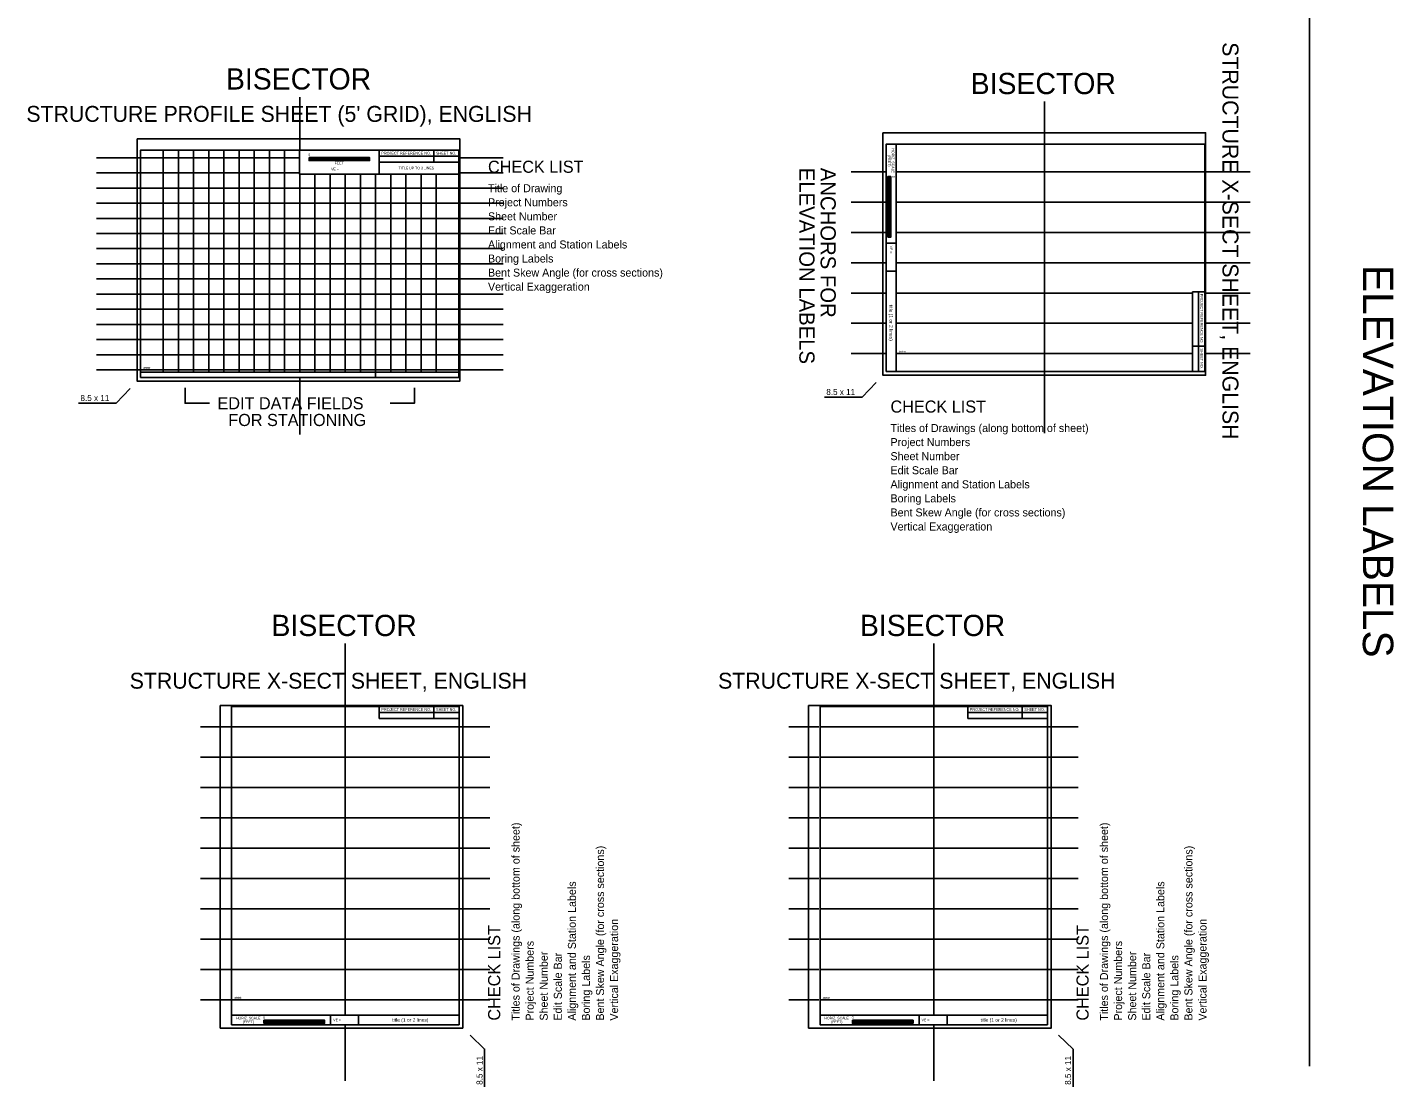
# Model space of a CAD drawing. Extents: x 278618 to 280654, y 171155 to 171855.
# Drawn here: x 278748.3 to 279198.9, y 171155.2 to 171504.7 of the extents above; entities that cross this region are included whole.
import ezdxf

# ---------------------------------------------------------------- set-up
doc = ezdxf.new("R2010")
doc.units = 0
for name, color, linetype in [('Geotech Sheets and Borders Cell', 7, 'Continuous'), ('Prop Strc Sect_ Grid - minor', 7, 'Continuous'), ('Prop Strc Sect_ Misc - Drafting Aid (dashed line)', 7, 'Continuous'), ('Prop Strc Sect_ Misc - User Comment (Tx - large)', 7, 'Continuous'), ('Prop Strc Sect_ Misc - User Comment (Tx - small)', 7, 'Continuous'), ('Scratch_Level_0', 7, 'Continuous'), ('Scratch_Level_2', 7, 'Continuous'), ('Scratch_Level_4', 7, 'Continuous'), ('Sheet Dot Grid CELL', 7, 'Continuous'), ('Sheet Plot Border Inside CELL', 7, 'Continuous')]:
    doc.layers.add(name, color=color, linetype=linetype)

msp = doc.modelspace()

# ---------------------------------------------------------------- linework, layer by layer
at = {"layer": 'Geotech Sheets and Borders Cell'}
for p, q in [((278864.34, 171462.15), (278890.63, 171462.15)), ((278882.35, 171464.15), (278882.35, 171460.15)), ((279034.8, 171433.49), (279031.59, 171433.49)), ((279034.8, 171433.49), (279031.59, 171433.49)), ((279034.8, 171424.26), (279031.59, 171424.26)), ((279134.59, 171417.45), (279134.59, 171391.15)), ((279136.59, 171399.44), (279132.59, 171399.44)), ((278785.63, 171390.92), (278890.63, 171390.92)), ((278864.36, 171278.64), (278890.66, 171278.64)), ((278882.37, 171280.64), (278882.37, 171276.64)), ((279058.42, 171278.64), (279084.72, 171278.64)), ((279076.43, 171280.64), (279076.43, 171276.64)), ((278848.32, 171178.85), (278848.32, 171175.64)), ((278848.32, 171178.85), (278848.32, 171175.64)), ((278857.55, 171178.85), (278857.55, 171175.64)), ((279042.38, 171178.85), (279042.38, 171175.64)), ((279042.38, 171178.85), (279042.38, 171175.64)), ((279051.61, 171178.85), (279051.61, 171175.64))]:
    msp.add_line(p, q, dxfattribs=at)
for points in [[(278890.63, 171464.15), (278890.63, 171389.15), (278785.63, 171389.15), (278785.63, 171464.15)], [(278838.04, 171456.25), (278890.63, 171456.25), (278890.63, 171464.15), (278838.04, 171464.15)], [(278864.34, 171460.15), (278890.63, 171460.15), (278890.63, 171464.15), (278864.34, 171464.15)], [(278864.34, 171464.15), (278890.63, 171464.15), (278890.63, 171456.25), (278864.34, 171456.25)], [(279136.59, 171466.15), (279136.59, 171391.15), (279031.59, 171391.15), (279031.59, 171466.15)], [(279034.8, 171466.15), (279034.8, 171391.15), (279031.59, 171391.15), (279031.59, 171466.15)], [(278841.19, 171461.69), (278861.19, 171461.69), (278861.19, 171460.69), (278841.19, 171460.69)], [(278841.19, 171461.69), (278851.19, 171461.69), (278851.19, 171461.19), (278841.19, 171461.19)], [(278851.19, 171461.19), (278861.19, 171461.19), (278861.19, 171460.69), (278851.19, 171460.69)], [(279033.09, 171455.47), (279033.09, 171435.47), (279032.09, 171435.47), (279032.09, 171455.47)], [(279033.09, 171455.47), (279033.09, 171445.47), (279032.59, 171445.47), (279032.59, 171455.47)], [(279032.59, 171445.47), (279032.59, 171435.47), (279032.09, 171435.47), (279032.09, 171445.47)], [(279132.59, 171417.45), (279132.59, 171391.15), (279136.59, 171391.15), (279136.59, 171417.45)], [(278815.66, 171280.64), (278890.66, 171280.64), (278890.66, 171175.64), (278815.66, 171175.64)], [(278864.36, 171276.64), (278890.66, 171276.64), (278890.66, 171280.64), (278864.36, 171280.64)], [(279009.72, 171280.64), (279084.72, 171280.64), (279084.72, 171175.64), (279009.72, 171175.64)], [(279058.42, 171276.64), (279084.72, 171276.64), (279084.72, 171280.64), (279058.42, 171280.64)], [(278815.66, 171178.85), (278890.66, 171178.85), (278890.66, 171175.64), (278815.66, 171175.64)], [(279009.72, 171178.85), (279084.72, 171178.85), (279084.72, 171175.64), (279009.72, 171175.64)], [(278826.34, 171177.14), (278846.34, 171177.14), (278846.34, 171176.14), (278826.34, 171176.14)], [(278826.34, 171177.14), (278836.34, 171177.14), (278836.34, 171176.64), (278826.34, 171176.64)], [(278836.34, 171176.64), (278846.34, 171176.64), (278846.34, 171176.14), (278836.34, 171176.14)], [(279020.4, 171177.14), (279040.4, 171177.14), (279040.4, 171176.14), (279020.4, 171176.14)], [(279020.4, 171177.14), (279030.4, 171177.14), (279030.4, 171176.64), (279020.4, 171176.64)], [(279030.4, 171176.64), (279040.4, 171176.64), (279040.4, 171176.14), (279030.4, 171176.14)]]:
    msp.add_lwpolyline(points, close=True, dxfattribs=at)
at = {"layer": 'Prop Strc Sect_ Grid - minor'}
for p, q in [((279136.59, 171457.02), (279034.8, 171457.02)), ((279136.59, 171447.02), (279034.8, 171447.02)), ((279136.59, 171437.02), (279034.8, 171437.02)), ((279136.59, 171427.02), (279034.8, 171427.02)), ((279132.59, 171417.02), (279034.8, 171417.02)), ((279132.59, 171407.02), (279034.8, 171407.02)), ((279132.59, 171397.02), (279034.8, 171397.02)), ((278890.66, 171273.96), (278815.66, 171273.96)), ((279084.72, 171273.96), (279009.72, 171273.96)), ((278890.66, 171263.96), (278815.66, 171263.96)), ((279084.72, 171263.96), (279009.72, 171263.96)), ((278890.66, 171253.95), (278815.66, 171253.95)), ((279084.72, 171253.95), (279009.72, 171253.95)), ((278890.66, 171243.93), (278815.66, 171243.93)), ((279084.72, 171243.93), (279009.72, 171243.93)), ((278890.66, 171233.92), (278815.66, 171233.92)), ((279084.72, 171233.92), (279009.72, 171233.92)), ((278890.66, 171223.91), (278815.66, 171223.91)), ((279084.72, 171223.91), (279009.72, 171223.91)), ((278890.66, 171213.9), (278815.66, 171213.9)), ((279084.72, 171213.9), (279009.72, 171213.9)), ((278890.66, 171203.88), (278815.66, 171203.88)), ((279084.72, 171203.88), (279009.72, 171203.88)), ((278890.66, 171193.87), (278815.66, 171193.87)), ((279084.72, 171193.87), (279009.72, 171193.87)), ((278890.66, 171183.86), (278815.66, 171183.86)), ((279084.72, 171183.86), (279009.72, 171183.86))]:
    msp.add_line(p, q, dxfattribs=at)
at = {"layer": 'Prop Strc Sect_ Misc - Drafting Aid (dashed line)'}
for p, q in [((278838.13, 171481.66), (278838.13, 171464.15)), ((279083.74, 171480.14), (279083.74, 171370.82)), ((278787.47, 171461.65), (278771.08, 171461.65)), ((278890.63, 171461.65), (278905.18, 171461.65)), ((278787.47, 171456.65), (278771.08, 171456.65)), ((278838.13, 171456.25), (278838.13, 171390.92)), ((278890.63, 171456.65), (278905.18, 171456.65)), ((279031.59, 171457.02), (279019.97, 171457.02)), ((279036.88, 171457.02), (279034.8, 171457.02)), ((279151.56, 171457.02), (279134.64, 171457.02)), ((278787.47, 171451.65), (278771.08, 171451.65)), ((278888.79, 171451.65), (278905.18, 171451.65)), ((278787.47, 171446.65), (278771.08, 171446.65)), ((278888.79, 171446.65), (278905.18, 171446.65)), ((279031.59, 171447.02), (279019.97, 171447.02)), ((279036.88, 171447.02), (279034.8, 171447.02)), ((279151.56, 171447.02), (279134.64, 171447.02)), ((278787.47, 171441.65), (278771.08, 171441.65)), ((278888.79, 171441.65), (278905.18, 171441.65)), ((278787.47, 171436.65), (278771.08, 171436.65)), ((278888.79, 171436.65), (278905.18, 171436.65)), ((279031.59, 171437.02), (279019.97, 171437.02)), ((279036.88, 171437.02), (279034.8, 171437.02)), ((279151.56, 171437.02), (279134.64, 171437.02)), ((278787.47, 171431.65), (278771.08, 171431.65)), ((278888.79, 171431.65), (278905.18, 171431.65)), ((278787.47, 171426.65), (278771.08, 171426.65)), ((278888.79, 171426.65), (278905.18, 171426.65)), ((279031.59, 171427.02), (279019.97, 171427.02)), ((279036.88, 171427.02), (279034.8, 171427.02)), ((279151.56, 171427.02), (279134.64, 171427.02)), ((278787.47, 171421.65), (278771.08, 171421.65)), ((278888.79, 171421.65), (278905.18, 171421.65)), ((279031.59, 171417.02), (279019.97, 171417.02)), ((279036.88, 171417.02), (279034.8, 171417.02)), ((279151.56, 171417.02), (279136.59, 171417.02)), ((278787.47, 171416.65), (278771.08, 171416.65)), ((278888.79, 171416.65), (278905.18, 171416.65)), ((278787.47, 171411.65), (278771.08, 171411.65)), ((278888.79, 171411.65), (278905.18, 171411.65)), ((278787.47, 171406.65), (278771.08, 171406.65)), ((278888.79, 171406.65), (278905.18, 171406.65)), ((279031.59, 171407.02), (279019.97, 171407.02)), ((279036.88, 171407.02), (279034.8, 171407.02)), ((279151.56, 171407.02), (279136.59, 171407.02)), ((278787.47, 171401.65), (278771.08, 171401.65)), ((278888.79, 171401.65), (278905.18, 171401.65)), ((278787.47, 171396.65), (278771.08, 171396.65)), ((278888.79, 171396.65), (278905.18, 171396.65)), ((279031.59, 171397.02), (279019.97, 171397.02)), ((279036.88, 171397.02), (279034.8, 171397.02)), ((279151.56, 171397.02), (279136.59, 171397.02)), ((278787.47, 171391.65), (278771.08, 171391.65)), ((278888.79, 171391.65), (278905.18, 171391.65)), ((278838.13, 171389.15), (278838.13, 171370.32)), ((278853.16, 171301.38), (278853.16, 171178.85)), ((279047.22, 171301.38), (279047.22, 171178.85)), ((278805.36, 171273.96), (278815.26, 171273.96)), ((278890.88, 171273.96), (278900.79, 171273.96)), ((278999.42, 171273.96), (279009.32, 171273.96)), ((279084.94, 171273.97), (279094.84, 171273.97)), ((278805.36, 171263.96), (278815.26, 171263.96)), ((278890.88, 171263.96), (278900.79, 171263.96)), ((278999.42, 171263.96), (279009.32, 171263.96)), ((279084.94, 171263.96), (279094.84, 171263.96)), ((278805.36, 171253.95), (278815.26, 171253.95)), ((278890.88, 171253.95), (278900.79, 171253.95)), ((278999.42, 171253.95), (279009.32, 171253.95)), ((279084.94, 171253.95), (279094.84, 171253.95)), ((278805.36, 171243.93), (278815.26, 171243.93)), ((278890.88, 171243.93), (278900.79, 171243.93)), ((278999.42, 171243.93), (279009.32, 171243.93)), ((279084.94, 171243.93), (279094.84, 171243.93)), ((278805.36, 171233.92), (278815.26, 171233.92)), ((278890.88, 171233.92), (278900.79, 171233.92)), ((278999.42, 171233.92), (279009.32, 171233.92)), ((279084.94, 171233.92), (279094.84, 171233.92)), ((278805.36, 171223.91), (278815.26, 171223.91)), ((278890.88, 171223.91), (278900.79, 171223.91)), ((278999.42, 171223.91), (279009.32, 171223.91)), ((279084.94, 171223.91), (279094.84, 171223.91)), ((278805.36, 171213.9), (278815.26, 171213.9)), ((278890.88, 171213.9), (278900.79, 171213.9)), ((278999.42, 171213.9), (279009.32, 171213.9)), ((279084.94, 171213.9), (279094.84, 171213.9)), ((278805.36, 171203.88), (278815.26, 171203.88)), ((278890.88, 171203.88), (278900.79, 171203.88)), ((278999.42, 171203.88), (279009.32, 171203.88)), ((279084.94, 171203.88), (279094.84, 171203.88)), ((278805.36, 171193.87), (278815.26, 171193.87)), ((278890.88, 171193.87), (278900.79, 171193.87)), ((278999.42, 171193.87), (279009.32, 171193.87)), ((279084.94, 171193.87), (279094.84, 171193.87)), ((278805.36, 171183.86), (278815.26, 171183.86)), ((278890.88, 171183.86), (278900.79, 171183.86)), ((278999.42, 171183.86), (279009.32, 171183.86)), ((279084.94, 171183.86), (279094.84, 171183.86)), ((278853.16, 171175.64), (278853.16, 171157.13)), ((279047.22, 171175.64), (279047.22, 171157.13))]:
    msp.add_line(p, q, dxfattribs=at)
at = {"layer": 'Prop Strc Sect_ Misc - User Comment (Tx - large)'}
msp.add_line((279171.15, 171633.82), (279171.15, 171161.99), dxfattribs=at)
at = {"layer": 'Scratch_Level_0'}
for p, q in [((278890.92, 171467.9), (278890.92, 171467.9)), ((279136.88, 171469.9), (279136.88, 171469.9)), ((279030.48, 171389.9), (279030.48, 171389.9)), ((278784.52, 171387.9), (278784.52, 171387.9)), ((278811.91, 171280.93), (278811.91, 171280.93)), ((279005.97, 171280.93), (279005.97, 171280.93)), ((278891.91, 171174.53), (278891.91, 171174.53)), ((279085.97, 171174.53), (279085.97, 171174.53))]:
    msp.add_line(p, q, dxfattribs=at)
for points in [[(278765.21, 171380.71), (278777.63, 171380.71), (278782.22, 171385.51)], [(279011.17, 171382.71), (279023.6, 171382.71), (279028.19, 171387.51)], [(278899.1, 171155.22), (278899.1, 171167.64), (278894.3, 171172.24)], [(279093.16, 171155.22), (279093.16, 171167.64), (279088.36, 171172.24)]]:
    msp.add_lwpolyline(points, dxfattribs=at)
at = {"layer": 'Scratch_Level_4'}
for points in [[(278808.34, 171380.66), (278800.31, 171380.66), (278800.31, 171385.74)], [(278867.93, 171380.66), (278875.96, 171380.66), (278875.96, 171385.74)]]:
    msp.add_lwpolyline(points, dxfattribs=at)
at = {"layer": 'Sheet Dot Grid CELL'}
for p, q in [((278793.13, 171464.15), (278793.13, 171390.92)), ((278798.13, 171464.15), (278798.13, 171390.92)), ((278803.13, 171464.15), (278803.13, 171390.92)), ((278808.13, 171464.15), (278808.13, 171390.92)), ((278813.13, 171464.15), (278813.13, 171390.92)), ((278818.13, 171464.15), (278818.13, 171390.92)), ((278823.13, 171464.15), (278823.13, 171390.92)), ((278828.13, 171464.15), (278828.13, 171390.92)), ((278833.13, 171464.15), (278833.13, 171390.92)), ((278785.63, 171461.65), (278838.04, 171461.65)), ((278785.63, 171456.65), (278838.04, 171456.65)), ((278838.13, 171456.25), (278838.13, 171390.92)), ((278843.13, 171456.25), (278843.13, 171390.92)), ((278848.13, 171456.25), (278848.13, 171390.92)), ((278853.13, 171456.25), (278853.13, 171390.92)), ((278858.13, 171456.25), (278858.13, 171390.92)), ((278863.13, 171456.25), (278863.13, 171389.03)), ((278868.13, 171456.25), (278868.13, 171390.92)), ((278873.13, 171456.25), (278873.13, 171390.92)), ((278878.13, 171456.25), (278878.13, 171390.92)), ((278883.13, 171456.25), (278883.13, 171390.92)), ((278785.63, 171451.65), (278890.63, 171451.65)), ((278785.63, 171446.65), (278890.63, 171446.65)), ((278785.63, 171441.65), (278890.63, 171441.65)), ((278785.63, 171436.65), (278890.63, 171436.65)), ((278785.63, 171431.65), (278890.63, 171431.65)), ((278785.63, 171426.65), (278890.63, 171426.65)), ((278785.63, 171421.65), (278890.63, 171421.65)), ((278785.63, 171416.65), (278890.63, 171416.65)), ((278785.63, 171411.65), (278890.63, 171411.65)), ((278785.63, 171406.65), (278890.63, 171406.65)), ((278785.63, 171401.65), (278890.63, 171401.65)), ((278785.63, 171396.65), (278890.63, 171396.65)), ((278785.63, 171391.65), (278890.63, 171391.65))]:
    msp.add_line(p, q, dxfattribs=at)
at = {"layer": 'Sheet Plot Border Inside CELL'}
for points in [[(278784.52, 171467.9), (278784.52, 171387.9), (278890.92, 171387.9), (278890.92, 171467.9)], [(279030.48, 171469.9), (279030.48, 171389.9), (279136.88, 171389.9), (279136.88, 171469.9)], [(278811.91, 171174.53), (278891.91, 171174.53), (278891.91, 171280.93), (278811.91, 171280.93)], [(279005.97, 171174.53), (279085.97, 171174.53), (279085.97, 171280.93), (279005.97, 171280.93)]]:
    msp.add_lwpolyline(points, close=True, dxfattribs=at)

# ---------------------------------------------------------------- texts
at = {"layer": 'Geotech Sheets and Borders Cell'}
for s, height, p in [('0', 0.84, (278840.95, 171462.17)), ('PROJECT REFERENCE NO.', 0.9, (278865.05, 171462.7)), ('SHEET NO.', 0.9, (278883.06, 171462.7)), ('VE =  ', 0.84, (278848.48, 171457.47)), ('FEET', 0.84, (278849.64, 171459.47)), ('###', 1.001, (279035.7, 171397.02)), ('###', 1.001, (278786.53, 171391.65)), ('###', 1.001, (278816.56, 171183.86)), ('###', 1.001, (279010.61, 171183.86))]:
    msp.add_text(s, height=height, dxfattribs=at).set_placement(p)
for s, height, rotation, p in [('(FEET)', 0.84, 270, (279032.13, 171462.5)), ('HORIZ. SCALE', 0.84, 270, (279033.38, 171464.71)), ('TITLE UP TO 3 LINES', 0.84, 360, (278870.76, 171457.81)), ('0', 0.84, 270, (279033.56, 171455.71)), ('VE =  ', 0.84, 270, (279032.76, 171432.64)), ('title (1 or 2 lines) ', 1.1681, 270, (279032.59, 171413.16)), ('PROJECT REFERENCE NO.', 0.9, 270, (279135.14, 171416.74)), ('SHEET NO.', 0.9, 270, (279135.14, 171398.73)), ('PROJECT REFERENCE NO.', 0.9, 360, (278865.07, 171279.19)), ('SHEET NO.', 0.9, 360, (278883.08, 171279.19)), ('PROJECT REFERENCE NO.', 0.9, 360, (279059.13, 171279.19)), ('SHEET NO.', 0.9, 360, (279077.14, 171279.19)), ('HORIZ. SCALE', 0.84, 360, (278817.1, 171177.42)), ('0', 0.84, 360, (278826.1, 171177.61)), ('HORIZ. SCALE', 0.84, 360, (279011.16, 171177.42)), ('0', 0.84, 360, (279020.16, 171177.61)), ('(FEET)', 0.84, 360, (278819.31, 171176.18)), ('VE =  ', 0.84, 360, (278849.17, 171176.8)), ('title (1 or 2 lines) ', 1.1681, 360, (278868.65, 171176.64)), ('(FEET)', 0.84, 360, (279013.37, 171176.18)), ('VE =  ', 0.84, 360, (279043.23, 171176.8)), ('title (1 or 2 lines) ', 1.1681, 360, (279062.71, 171176.64))]:
    msp.add_text(s, height=height, rotation=rotation, dxfattribs=at).set_placement(p)
at = {"layer": 'Prop Strc Sect_ Misc - User Comment (Tx - small)'}
for p in [(278813.79, 171484.14), (279059.4, 171482.62), (278828.81, 171303.86), (279022.87, 171303.86)]:
    msp.add_text('BISECTOR', height=7.009, dxfattribs=at).set_placement(p)
for s, height, p in [('ELEVATION LABELS', 5.0062, (279002.9, 171458.33)), ('ANCHORS FOR', 5.0062, (279009.91, 171458.33)), ('ELEVATION LABELS', 10.0124, (279188.75, 171426.25))]:
    msp.add_text(s, height=height, rotation=270, dxfattribs=at).set_placement(p)
at = {"layer": 'Scratch_Level_0'}
for p in [(279011.79, 171383.38), (278765.82, 171381.38)]:
    msp.add_text('8.5 x 11', height=2, dxfattribs=at).set_placement(p)
for p in [(278898.43, 171155.83), (279092.49, 171155.83)]:
    msp.add_text('8.5 x 11', height=2, rotation=90, dxfattribs=at).set_placement(p)
at = {"layer": 'Scratch_Level_2'}
for rotation, p in [(270, (279142.46, 171499.75)), (360, (278782.05, 171286.51)), (360, (278976.11, 171286.51))]:
    msp.add_text('STRUCTURE X-SECT SHEET, ENGLISH', height=5.25, rotation=rotation, dxfattribs=at).set_placement(p)
msp.add_text("STRUCTURE PROFILE SHEET (5' GRID), ENGLISH", height=5.25, dxfattribs=at).set_placement((278747.97, 171473.48))
at = {"layer": 'Scratch_Level_4'}
for s, height, p in [('CHECK LIST', 4, (278900.22, 171456.67)), ('Title of Drawing', 2.64, (278900.22, 171450.27)), ('Project Numbers', 2.64, (278900.22, 171445.63)), ('Sheet Number', 2.64, (278900.22, 171440.99)), ('Edit Scale Bar', 2.64, (278900.22, 171436.35)), ('Alignment and Station Labels', 2.64, (278900.22, 171431.71)), ('Boring Labels', 2.64, (278900.22, 171427.07)), ('Bent Skew Angle (for cross sections)', 2.64, (278900.22, 171422.43)), ('Vertical Exaggeration', 2.64, (278900.22, 171417.79)), ('EDIT DATA FIELDS', 4, (278811.01, 171378.66)), ('CHECK LIST', 4, (279032.96, 171377.56)), ('FOR STATIONING', 4, (278814.57, 171373.14)), ('Titles of Drawings (along bottom of sheet)', 2.64, (279032.96, 171371.16)), ('Project Numbers', 2.64, (279032.96, 171366.52)), ('Sheet Number', 2.64, (279032.96, 171361.88)), ('Edit Scale Bar', 2.64, (279032.96, 171357.24)), ('Alignment and Station Labels', 2.64, (279032.96, 171352.6)), ('Boring Labels', 2.64, (279032.96, 171347.96)), ('Bent Skew Angle (for cross sections)', 2.64, (279032.96, 171343.32)), ('Vertical Exaggeration', 2.64, (279032.96, 171338.68))]:
    msp.add_text(s, height=height, dxfattribs=at).set_placement(p)
for s, height, p in [('Titles of Drawings (along bottom of sheet)', 2.64, (278910.65, 171177.01)), ('Titles of Drawings (along bottom of sheet)', 2.64, (279104.71, 171177.01)), ('Bent Skew Angle (for cross sections)', 2.64, (278938.49, 171177.01)), ('Bent Skew Angle (for cross sections)', 2.64, (279132.55, 171177.01)), ('Alignment and Station Labels', 2.64, (278929.21, 171177.01)), ('Alignment and Station Labels', 2.64, (279123.27, 171177.01)), ('Vertical Exaggeration', 2.64, (278943.13, 171177.01)), ('Vertical Exaggeration', 2.64, (279137.19, 171177.01)), ('CHECK LIST', 4, (278904.25, 171177.01)), ('CHECK LIST', 4, (279098.31, 171177.01)), ('Project Numbers', 2.64, (278915.29, 171177.01)), ('Project Numbers', 2.64, (279109.35, 171177.01)), ('Sheet Number', 2.64, (278919.93, 171177.01)), ('Edit Scale Bar', 2.64, (278924.57, 171177.01)), ('Boring Labels', 2.64, (278933.85, 171177.01)), ('Sheet Number', 2.64, (279113.99, 171177.01)), ('Edit Scale Bar', 2.64, (279118.63, 171177.01)), ('Boring Labels', 2.64, (279127.91, 171177.01))]:
    msp.add_text(s, height=height, rotation=90, dxfattribs=at).set_placement(p)

doc.saveas('drawing.dxf')
